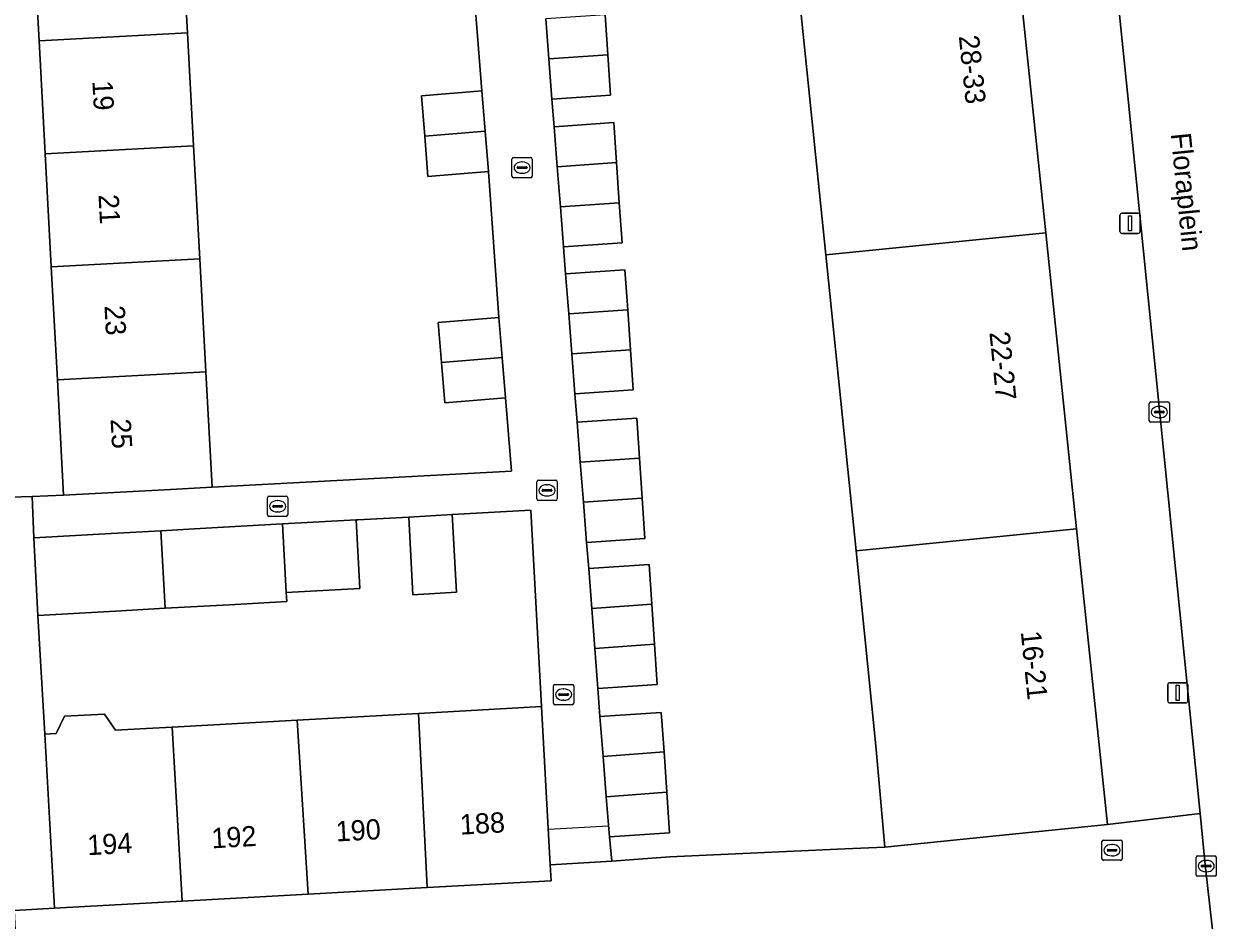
# Model space of a CAD drawing. Extents: x 162250 to 162661, y 380743 to 381606.
# Drawn here: x 162500.7 to 162559.6, y 380777.6 to 380821.9 of the extents above; entities that cross this region are included whole.
import ezdxf

# ---------------------------------------------------------------- set-up
doc = ezdxf.new("R2010")
doc.units = 0
for name, color, linetype in [('IMGEO_Brandkraan', 7, 'Continuous'), ('IMGEO_Erf', 7, 'Continuous'), ('IMGEO_Hek', 7, 'Continuous'), ('IMGEO_Kolk', 7, 'Continuous'), ('IMGEO_Lichtmast', 7, 'Continuous'), ('IMGEO_Muur', 7, 'Continuous'), ('IMGEO_Openbare_ruimte_label', 7, 'Continuous'), ('IMGEO_Pand', 7, 'Continuous'), ('IMGEO_Pand_nummerreeks', 7, 'Continuous'), ('IMGEO_Rijbaan_lokaal_open', 7, 'Continuous'), ('IMGEO_Voetpad_open', 7, 'Continuous')]:
    doc.layers.add(name, color=color, linetype=linetype)

msp = doc.modelspace()

# ---------------------------------------------------------------- linework, layer by layer
at = {"layer": 'IMGEO_Brandkraan'}
for p, q in [((162553.929, 380780.603), (162553.929, 380781.455)), ((162554.004, 380781.529), (162554.856, 380781.529)), ((162554.93, 380781.455), (162554.93, 380780.603)), ((162554.188, 380781.023), (162554.188, 380781.035)), ((162554.626, 380780.986), (162554.228, 380780.986)), ((162554.231, 380781.072), (162554.629, 380781.072)), ((162554.417, 380781.309), (162554.442, 380781.309)), ((162554.672, 380781.035), (162554.672, 380781.023)), ((162554.856, 380780.529), (162554.004, 380780.529)), ((162554.44, 380780.749), (162554.415, 380780.749))]:
    msp.add_line(p, q, dxfattribs=at)
for points in [[(162553.929, 380780.603), (162553.929, 380781.455)], [(162554.004, 380781.529), (162554.856, 380781.529)], [(162554.93, 380781.455), (162554.93, 380780.603)], [(162554.856, 380780.529), (162554.004, 380780.529)]]:
    msp.add_lwpolyline(points, dxfattribs=at)
for centre, radius, start, end in [((162554.006, 380781.453), 0.0765, 91.55205, 178.44795), ((162554.006, 380781.453), 0.0765, 91.55205, 178.44795), ((162554.854, 380781.453), 0.0765, 1.55205, 88.44795), ((162554.854, 380781.453), 0.0765, 1.55205, 88.44795), ((162554.228, 380781.032), 0.0403, 85.87752, 175.75265), ((162554.225, 380781.022), 0.0366, 178.93798, 274.71019), ((162554.629, 380781.029), 0.043, 264.86636, 352.45326), ((162554.633, 380781.034), 0.0386, 1.73085, 96.63898), ((162554.006, 380780.605), 0.0765, 181.55205, 268.44795), ((162554.006, 380780.605), 0.0765, 181.55205, 268.44795), ((162554.854, 380780.605), 0.0765, 271.55205, 358.44795), ((162554.854, 380780.605), 0.0765, 271.55205, 358.44795)]:
    msp.add_arc(centre, radius, start, end, dxfattribs=at)
for centre, major_axis, ratio, start_param, end_param in [((162554.416, 380781.029), (-0.387, 0.002), 0.722429, 4.712389, 7.853982), ((162554.441, 380781.029), (-0.39, 0.002), 0.717154, 1.570796, 4.712389)]:
    msp.add_ellipse(centre, major_axis=major_axis, ratio=ratio, start_param=start_param, end_param=end_param, dxfattribs=at)
at = {"layer": 'IMGEO_Erf'}
for points in [[(162500.535, 380837.761), (162500.235, 380843.344), (162500, 380847.679), (162499.934, 380848.927), (162499.634, 380854.509), (162499.333, 380860.091), (162499.032, 380865.673), (162498.723, 380871.373), (162496.735, 380871.229), (162495.691, 380871.164), (162499.625, 380798.455), (162500, 380798.466), (162501.095, 380798.5), (162502.647, 380798.565), (162502.34, 380804.267), (162502.039, 380809.849), (162501.738, 380815.432), (162501.437, 380821.014), (162501.136, 380826.596), (162500.835, 380832.179)], [(162525.72, 380797.824), (162521.84, 380797.61), (162522.052, 380793.775), (162519.891, 380793.655), (162519.7, 380797.492), (162517.176, 380797.352), (162517.097, 380797.348), (162517.284, 380793.96), (162513.649, 380793.759), (162513.674, 380793.313), (162510.849, 380793.157), (162507.673, 380792.981), (162505.216, 380792.845), (162501.383, 380792.633), (162501.726, 380786.77), (162502.28, 380786.8), (162502.694, 380787.646), (162504.665, 380787.754), (162505.219, 380786.961), (162506.735, 380787.044), (162508.012, 380787.115), (162514.19, 380787.456), (162520.184, 380787.787), (162526.255, 380788.122)]]:
    msp.add_lwpolyline(points, close=True, dxfattribs=at)
for points in [[(162508.463, 380826.992), (162508.766, 380821.409), (162509.07, 380815.828), (162509.373, 380810.246), (162509.676, 380804.664), (162509.986, 380798.963), (162524.762, 380799.763), (162524.467, 380803.379), (162521.477, 380803.135), (162521.315, 380805.122), (162521.153, 380807.109), (162524.143, 380807.353), (162523.636, 380814.568), (162520.646, 380814.324), (162520.484, 380816.311), (162520.322, 380818.298), (162523.312, 380818.542), (162522.731, 380825.847)], [(162529.396, 380822.302), (162529.531, 380820.322), (162529.666, 380818.342), (162526.77, 380818.142), (162526.876, 380816.777), (162529.825, 380816.981), (162529.96, 380815.001), (162530.095, 380813.021), (162530.23, 380811.041), (162527.337, 380810.844), (162527.441, 380809.503), (162530.374, 380809.709), (162530.509, 380807.729), (162530.644, 380805.749), (162530.779, 380803.769), (162527.902, 380803.573), (162528.01, 380802.18), (162530.953, 380802.378), (162531.088, 380800.398), (162531.223, 380798.418), (162531.358, 380796.438), (162528.472, 380796.238), (162528.589, 380794.948), (162531.562, 380795.151), (162531.696, 380793.19), (162531.831, 380791.21), (162531.967, 380789.211), (162529.033, 380789.011), (162529.141, 380787.631), (162532.17, 380787.835), (162532.303, 380785.885), (162532.438, 380783.904), (162532.575, 380781.895), (162529.602, 380781.692), (162529.724, 380780.491), (162532.594, 380780.706), (162541.237, 380781.095), (162543.214, 380781.184), (162542.767, 380786.192), (162541.786, 380795.815), (162540.295, 380810.439), (162538.803, 380825.063)]]:
    msp.add_lwpolyline(points, dxfattribs=at)
at = {"layer": 'IMGEO_Hek'}
msp.add_lwpolyline([(162529.566, 380782.219), (162526.59, 380782.049)], dxfattribs=at)
at = {"layer": 'IMGEO_Kolk'}
for p, q in [((162524.794, 380814.329), (162524.794, 380815.181)), ((162524.869, 380815.255), (162525.721, 380815.255)), ((162525.282, 380815.035), (162525.307, 380815.035)), ((162525.795, 380815.181), (162525.795, 380814.329)), ((162525.053, 380814.749), (162525.053, 380814.761)), ((162525.491, 380814.712), (162525.093, 380814.712)), ((162525.096, 380814.798), (162525.494, 380814.798)), ((162525.305, 380814.475), (162525.28, 380814.475)), ((162525.537, 380814.761), (162525.537, 380814.749)), ((162525.721, 380814.255), (162524.869, 380814.255)), ((162556.267, 380802.249), (162556.267, 380803.101)), ((162556.342, 380803.175), (162557.194, 380803.175)), ((162556.526, 380802.669), (162556.526, 380802.681)), ((162556.964, 380802.632), (162556.566, 380802.632)), ((162556.569, 380802.718), (162556.967, 380802.718)), ((162556.755, 380802.955), (162556.78, 380802.955)), ((162557.01, 380802.681), (162557.01, 380802.669)), ((162557.268, 380803.101), (162557.268, 380802.249)), ((162557.194, 380802.175), (162556.342, 380802.175)), ((162556.778, 380802.395), (162556.753, 380802.395)), ((162526.026, 380798.384), (162526.026, 380799.236)), ((162526.101, 380799.31), (162526.953, 380799.31)), ((162526.514, 380799.09), (162526.539, 380799.09)), ((162527.027, 380799.236), (162527.027, 380798.384)), ((162512.793, 380798.521), (162513.645, 380798.521)), ((162526.285, 380798.804), (162526.285, 380798.816)), ((162526.723, 380798.767), (162526.325, 380798.767)), ((162526.328, 380798.853), (162526.726, 380798.853)), ((162526.537, 380798.53), (162526.512, 380798.53)), ((162526.769, 380798.816), (162526.769, 380798.804)), ((162512.718, 380797.595), (162512.718, 380798.447)), ((162512.977, 380798.015), (162512.977, 380798.027)), ((162513.415, 380797.978), (162513.017, 380797.978)), ((162513.02, 380798.064), (162513.418, 380798.064)), ((162513.206, 380798.301), (162513.231, 380798.301)), ((162513.461, 380798.027), (162513.461, 380798.015)), ((162513.719, 380798.447), (162513.719, 380797.595)), ((162526.953, 380798.31), (162526.101, 380798.31)), ((162513.645, 380797.521), (162512.793, 380797.521)), ((162513.229, 380797.741), (162513.204, 380797.741)), ((162526.842, 380788.293), (162526.842, 380789.145)), ((162526.917, 380789.219), (162527.769, 380789.219)), ((162527.843, 380789.145), (162527.843, 380788.293)), ((162527.101, 380788.713), (162527.101, 380788.725)), ((162527.539, 380788.676), (162527.141, 380788.676)), ((162527.144, 380788.762), (162527.542, 380788.762)), ((162527.33, 380788.999), (162527.355, 380788.999)), ((162527.585, 380788.725), (162527.585, 380788.713)), ((162527.769, 380788.219), (162526.917, 380788.219)), ((162527.353, 380788.439), (162527.328, 380788.439)), ((162558.58, 380779.817), (162558.58, 380780.669)), ((162558.655, 380780.743), (162559.507, 380780.743)), ((162558.839, 380780.237), (162558.839, 380780.249)), ((162558.882, 380780.286), (162559.28, 380780.286)), ((162559.068, 380780.523), (162559.093, 380780.523)), ((162559.323, 380780.249), (162559.323, 380780.237)), ((162559.581, 380780.669), (162559.581, 380779.817)), ((162559.507, 380779.743), (162558.655, 380779.743)), ((162559.277, 380780.2), (162558.879, 380780.2)), ((162559.091, 380779.963), (162559.066, 380779.963))]:
    msp.add_line(p, q, dxfattribs=at)
for points in [[(162524.794, 380814.329), (162524.794, 380815.181)], [(162524.869, 380815.255), (162525.721, 380815.255)], [(162525.795, 380815.181), (162525.795, 380814.329)], [(162525.721, 380814.255), (162524.869, 380814.255)], [(162556.267, 380802.249), (162556.267, 380803.101)], [(162556.342, 380803.175), (162557.194, 380803.175)], [(162557.268, 380803.101), (162557.268, 380802.249)], [(162557.194, 380802.175), (162556.342, 380802.175)], [(162526.026, 380798.384), (162526.026, 380799.236)], [(162526.101, 380799.31), (162526.953, 380799.31)], [(162527.027, 380799.236), (162527.027, 380798.384)], [(162512.793, 380798.521), (162513.645, 380798.521)], [(162512.718, 380797.595), (162512.718, 380798.447)], [(162513.719, 380798.447), (162513.719, 380797.595)], [(162526.953, 380798.31), (162526.101, 380798.31)], [(162513.645, 380797.521), (162512.793, 380797.521)], [(162526.842, 380788.293), (162526.842, 380789.145)], [(162526.917, 380789.219), (162527.769, 380789.219)], [(162527.843, 380789.145), (162527.843, 380788.293)], [(162527.769, 380788.219), (162526.917, 380788.219)], [(162558.58, 380779.817), (162558.58, 380780.669)], [(162558.655, 380780.743), (162559.507, 380780.743)], [(162559.581, 380780.669), (162559.581, 380779.817)], [(162559.507, 380779.743), (162558.655, 380779.743)]]:
    msp.add_lwpolyline(points, dxfattribs=at)
for centre, radius, start, end in [((162524.871, 380815.179), 0.0765, 91.55205, 178.44795), ((162524.871, 380815.179), 0.0765, 91.55205, 178.44795), ((162525.719, 380815.179), 0.0765, 1.55205, 88.44795), ((162525.719, 380815.179), 0.0765, 1.55205, 88.44795), ((162525.093, 380814.758), 0.0403, 85.87752, 175.75265), ((162525.09, 380814.748), 0.0366, 178.93798, 274.71019), ((162525.494, 380814.755), 0.043, 264.86636, 352.45326), ((162525.498, 380814.76), 0.0386, 1.73085, 96.63898), ((162524.871, 380814.331), 0.0765, 181.55205, 268.44795), ((162524.871, 380814.331), 0.0765, 181.55205, 268.44795), ((162525.719, 380814.331), 0.0765, 271.55205, 358.44795), ((162525.719, 380814.331), 0.0765, 271.55205, 358.44795), ((162556.344, 380803.099), 0.0765, 91.55205, 178.44795), ((162556.344, 380803.099), 0.0765, 91.55205, 178.44795), ((162556.566, 380802.678), 0.0403, 85.87752, 175.75265), ((162556.563, 380802.668), 0.0366, 178.93798, 274.71019), ((162556.967, 380802.675), 0.043, 264.86636, 352.45326), ((162556.971, 380802.68), 0.0386, 1.73085, 96.63898), ((162557.192, 380803.099), 0.0765, 1.55205, 88.44795), ((162557.192, 380803.099), 0.0765, 1.55205, 88.44795), ((162556.344, 380802.251), 0.0765, 181.55205, 268.44795), ((162556.344, 380802.251), 0.0765, 181.55205, 268.44795), ((162557.192, 380802.251), 0.0765, 271.55205, 358.44795), ((162557.192, 380802.251), 0.0765, 271.55205, 358.44795), ((162526.103, 380799.234), 0.0765, 91.55205, 178.44795), ((162526.103, 380799.234), 0.0765, 91.55205, 178.44795), ((162526.951, 380799.234), 0.0765, 1.55205, 88.44795), ((162526.951, 380799.234), 0.0765, 1.55205, 88.44795), ((162512.795, 380798.445), 0.0765, 91.55205, 178.44795), ((162512.795, 380798.445), 0.0765, 91.55205, 178.44795), ((162513.643, 380798.445), 0.0765, 1.55205, 88.44795), ((162513.643, 380798.445), 0.0765, 1.55205, 88.44795), ((162526.325, 380798.813), 0.0403, 85.87752, 175.75265), ((162526.322, 380798.803), 0.0366, 178.93798, 274.71019), ((162526.726, 380798.81), 0.043, 264.86636, 352.45326), ((162526.73, 380798.815), 0.0386, 1.73085, 96.63898), ((162513.017, 380798.024), 0.0403, 85.87752, 175.75265), ((162513.014, 380798.014), 0.0366, 178.93798, 274.71019), ((162513.418, 380798.021), 0.043, 264.86636, 352.45326), ((162513.422, 380798.026), 0.0386, 1.73085, 96.63898), ((162526.103, 380798.386), 0.0765, 181.55205, 268.44795), ((162526.103, 380798.386), 0.0765, 181.55205, 268.44795), ((162526.951, 380798.386), 0.0765, 271.55205, 358.44795), ((162526.951, 380798.386), 0.0765, 271.55205, 358.44795), ((162512.795, 380797.597), 0.0765, 181.55205, 268.44795), ((162512.795, 380797.597), 0.0765, 181.55205, 268.44795), ((162513.643, 380797.597), 0.0765, 271.55205, 358.44795), ((162513.643, 380797.597), 0.0765, 271.55205, 358.44795), ((162526.919, 380789.143), 0.0765, 91.55205, 178.44795), ((162526.919, 380789.143), 0.0765, 91.55205, 178.44795), ((162527.767, 380789.143), 0.0765, 1.55205, 88.44795), ((162527.767, 380789.143), 0.0765, 1.55205, 88.44795), ((162527.141, 380788.722), 0.0403, 85.87752, 175.75265), ((162527.138, 380788.712), 0.0366, 178.93798, 274.71019), ((162527.542, 380788.719), 0.043, 264.86636, 352.45326), ((162527.546, 380788.724), 0.0386, 1.73085, 96.63898), ((162526.919, 380788.295), 0.0765, 181.55205, 268.44795), ((162526.919, 380788.295), 0.0765, 181.55205, 268.44795), ((162527.767, 380788.295), 0.0765, 271.55205, 358.44795), ((162527.767, 380788.295), 0.0765, 271.55205, 358.44795), ((162558.657, 380780.667), 0.0765, 91.55205, 178.44795), ((162558.657, 380780.667), 0.0765, 91.55205, 178.44795), ((162558.879, 380780.246), 0.0403, 85.87752, 175.75265), ((162558.876, 380780.236), 0.0366, 178.93798, 274.71019), ((162559.28, 380780.243), 0.043, 264.86636, 352.45326), ((162559.284, 380780.248), 0.0386, 1.73085, 96.63898), ((162559.505, 380780.667), 0.0765, 1.55205, 88.44795), ((162559.505, 380780.667), 0.0765, 1.55205, 88.44795), ((162558.657, 380779.819), 0.0765, 181.55205, 268.44795), ((162558.657, 380779.819), 0.0765, 181.55205, 268.44795), ((162559.505, 380779.819), 0.0765, 271.55205, 358.44795), ((162559.505, 380779.819), 0.0765, 271.55205, 358.44795)]:
    msp.add_arc(centre, radius, start, end, dxfattribs=at)
for centre, major_axis, ratio, start_param, end_param in [((162525.281, 380814.755), (-0.387, 0.002), 0.722429, 4.712389, 7.853982), ((162525.306, 380814.755), (-0.39, 0.002), 0.717154, 1.570796, 4.712389), ((162556.754, 380802.675), (-0.387, 0.002), 0.722429, 4.712389, 7.853982), ((162556.779, 380802.675), (-0.39, 0.002), 0.717154, 1.570796, 4.712389), ((162526.513, 380798.81), (-0.387, 0.002), 0.722429, 4.712389, 7.853982), ((162526.538, 380798.81), (-0.39, 0.002), 0.717154, 1.570796, 4.712389), ((162513.205, 380798.021), (-0.387, 0.002), 0.722429, 4.712389, 7.853982), ((162513.23, 380798.021), (-0.39, 0.002), 0.717154, 1.570796, 4.712389), ((162527.329, 380788.719), (-0.387, 0.002), 0.722429, 4.712389, 7.853982), ((162527.354, 380788.719), (-0.39, 0.002), 0.717154, 1.570796, 4.712389), ((162559.067, 380780.243), (-0.387, 0.002), 0.722429, 4.712389, 7.853982), ((162559.092, 380780.243), (-0.39, 0.002), 0.717154, 1.570796, 4.712389)]:
    msp.add_ellipse(centre, major_axis=major_axis, ratio=ratio, start_param=start_param, end_param=end_param, dxfattribs=at)
at = {"layer": 'IMGEO_Lichtmast'}
for p, q in [((162554.822, 380811.603), (162554.822, 380812.403)), ((162554.822, 380812.403), (162554.822, 380811.603)), ((162554.922, 380812.503), (162555.712, 380812.503)), ((162555.712, 380812.503), (162554.922, 380812.503)), ((162555.812, 380812.403), (162555.812, 380811.603)), ((162555.812, 380811.603), (162555.812, 380812.403)), ((162555.712, 380811.503), (162554.922, 380811.503)), ((162554.922, 380811.503), (162555.712, 380811.503)), ((162557.182, 380788.406), (162557.182, 380789.206)), ((162557.182, 380789.206), (162557.182, 380788.406)), ((162557.282, 380789.306), (162558.072, 380789.306)), ((162558.072, 380789.306), (162557.282, 380789.306)), ((162558.172, 380789.206), (162558.172, 380788.406)), ((162558.172, 380788.406), (162558.172, 380789.206)), ((162558.072, 380788.306), (162557.282, 380788.306)), ((162557.282, 380788.306), (162558.072, 380788.306))]:
    msp.add_line(p, q, dxfattribs=at)
for points in [[(162555.242, 380812.378), (162555.392, 380812.378), (162555.392, 380811.628), (162555.242, 380811.628), (162555.242, 380812.378)], [(162557.602, 380789.181), (162557.752, 380789.181), (162557.752, 380788.431), (162557.602, 380788.431), (162557.602, 380789.181)]]:
    msp.add_lwpolyline(points, dxfattribs=at)
for centre, start, end in [((162554.922, 380812.403), 90, 180), ((162554.922, 380812.403), 90, 180), ((162555.712, 380812.403), 0, 90), ((162555.712, 380812.403), 360, 90), ((162554.922, 380811.603), 180, 270), ((162554.922, 380811.603), 180, 270), ((162555.712, 380811.603), 270, 0), ((162555.712, 380811.603), 270, 0), ((162557.282, 380789.206), 90, 180), ((162557.282, 380789.206), 90, 180), ((162558.072, 380789.206), 0, 90), ((162558.072, 380789.206), 360, 90), ((162557.282, 380788.406), 180, 270), ((162557.282, 380788.406), 180, 270), ((162558.072, 380788.406), 270, 0), ((162558.072, 380788.406), 270, 0)]:
    msp.add_arc(centre, 0.1, start, end, dxfattribs=at)
at = {"layer": 'IMGEO_Muur'}
for points in [[(162501.383, 380792.633), (162501.726, 380786.77)], [(162541.237, 380781.095), (162543.214, 380781.184)]]:
    msp.add_lwpolyline(points, dxfattribs=at)
at = {"layer": 'IMGEO_Pand'}
for points in [[(162508.463, 380826.992), (162501.136, 380826.596), (162501.437, 380821.014), (162508.766, 380821.409)], [(162551.156, 380811.537), (162549.634, 380826.158), (162538.803, 380825.063), (162540.295, 380810.439)], [(162529.396, 380822.302), (162526.462, 380822.102), (162526.616, 380820.123), (162529.531, 380820.322)], [(162508.766, 380821.409), (162501.437, 380821.014), (162501.738, 380815.432), (162509.07, 380815.828)], [(162529.531, 380820.322), (162526.616, 380820.123), (162526.77, 380818.142), (162529.666, 380818.342)], [(162523.312, 380818.542), (162520.322, 380818.298), (162520.484, 380816.311), (162523.474, 380816.555)], [(162529.825, 380816.981), (162526.876, 380816.777), (162527.03, 380814.801), (162529.96, 380815.001)], [(162523.474, 380816.555), (162520.484, 380816.311), (162520.646, 380814.324), (162523.636, 380814.568)], [(162501.738, 380815.432), (162502.039, 380809.849), (162509.373, 380810.246), (162509.07, 380815.828)], [(162529.96, 380815.001), (162527.03, 380814.801), (162527.183, 380812.822), (162530.095, 380813.021)], [(162530.095, 380813.021), (162527.183, 380812.822), (162527.337, 380810.844), (162530.23, 380811.041)], [(162551.156, 380811.537), (162540.295, 380810.439), (162541.786, 380795.815), (162552.678, 380796.916)], [(162509.676, 380804.664), (162509.373, 380810.246), (162502.039, 380809.849), (162502.34, 380804.267)], [(162530.374, 380809.709), (162527.441, 380809.503), (162527.594, 380807.53), (162530.509, 380807.729)], [(162524.143, 380807.353), (162521.153, 380807.109), (162521.315, 380805.122), (162524.305, 380805.366)], [(162530.509, 380807.729), (162527.594, 380807.53), (162527.748, 380805.552), (162530.644, 380805.749)], [(162530.644, 380805.749), (162527.748, 380805.552), (162527.902, 380803.573), (162530.779, 380803.769)], [(162524.305, 380805.366), (162521.315, 380805.122), (162521.477, 380803.135), (162524.467, 380803.379)], [(162509.676, 380804.664), (162502.34, 380804.267), (162502.647, 380798.565), (162507.64, 380798.836), (162509.986, 380798.963)], [(162530.953, 380802.378), (162528.01, 380802.18), (162528.164, 380800.199), (162531.088, 380800.398)], [(162531.088, 380800.398), (162528.164, 380800.199), (162528.318, 380798.22), (162531.223, 380798.418)], [(162531.223, 380798.418), (162528.318, 380798.22), (162528.472, 380796.238), (162531.358, 380796.438)], [(162517.097, 380797.348), (162513.462, 380797.148), (162513.649, 380793.759), (162517.284, 380793.96)], [(162519.7, 380797.492), (162519.891, 380793.655), (162522.052, 380793.775), (162521.84, 380797.61)], [(162507.673, 380792.981), (162507.451, 380796.815), (162505.004, 380796.68), (162501.171, 380796.468), (162501.383, 380792.633), (162505.216, 380792.845)], [(162513.462, 380797.148), (162509.668, 380796.938), (162507.451, 380796.815), (162507.673, 380792.981), (162510.849, 380793.157), (162513.674, 380793.313), (162513.649, 380793.759)], [(162541.786, 380795.815), (162542.767, 380786.192), (162543.214, 380781.184), (162554.2, 380782.295), (162552.678, 380796.916)], [(162528.589, 380794.948), (162528.737, 380792.969), (162531.696, 380793.19), (162531.562, 380795.151)], [(162531.696, 380793.19), (162528.737, 380792.969), (162528.885, 380790.99), (162531.831, 380791.21)], [(162531.831, 380791.21), (162528.885, 380790.99), (162529.033, 380789.011), (162531.967, 380789.211)], [(162520.184, 380787.787), (162520.613, 380779.182), (162526.73, 380779.52), (162526.687, 380780.301), (162526.454, 380784.513), (162526.255, 380788.122)], [(162508.012, 380787.115), (162506.735, 380787.044), (162505.219, 380786.961), (162504.665, 380787.754), (162502.694, 380787.646), (162502.28, 380786.8), (162501.726, 380786.77), (162502.201, 380778.165), (162508.51, 380778.514)], [(162508.012, 380787.115), (162508.51, 380778.514), (162514.735, 380778.857), (162514.19, 380787.456)], [(162520.184, 380787.787), (162514.19, 380787.456), (162514.735, 380778.857), (162520.613, 380779.182)], [(162529.141, 380787.631), (162529.295, 380785.651), (162532.303, 380785.885), (162532.17, 380787.835)], [(162532.303, 380785.885), (162529.295, 380785.651), (162529.448, 380783.672), (162532.438, 380783.904)], [(162532.438, 380783.904), (162529.448, 380783.672), (162529.602, 380781.692), (162532.575, 380781.895)]]:
    msp.add_lwpolyline(points, close=True, dxfattribs=at)
at = {"layer": 'IMGEO_Rijbaan_lokaal_open'}
msp.add_lwpolyline([(162556.408, 380848.385), (162556.384, 380848.613), (162556.077, 380851.576), (162555.417, 380857.25), (162555.382, 380857.554), (162550.999, 380857.103), (162551.063, 380856.512), (162551.932, 380848.95), (162553.575, 380834.204), (162555.189, 380818.45), (162558.777, 380782.848), (162559.034, 380780.302), (162559.621, 380775.057), (162559.501, 380773.592)], dxfattribs=at)
at = {"layer": 'IMGEO_Voetpad_open'}
for points in [[(162539.795, 380900.36), (162540.416, 380896.616), (162547.18, 380863.294), (162546.206, 380863.09), (162545.78, 380863.003), (162539.252, 380861.677), (162539.001, 380861.626), (162539.128, 380860.542), (162523.79, 380859.034), (162524.418, 380853.206), (162527.021, 380853.383), (162535.821, 380854.312), (162541.615, 380854.91), (162546.588, 380855.422), (162548.112, 380840.779), (162549.634, 380826.158), (162551.156, 380811.537), (162552.678, 380796.916), (162554.2, 380782.295), (162558.777, 380782.848), (162555.189, 380818.45), (162553.575, 380834.204), (162551.932, 380848.95)], [(162496.225, 380798.581), (162496.36, 380795.645), (162496.445, 380793.785), (162496.544, 380791.858), (162499.481, 380792.01), (162499.931, 380782.983), (162500.205, 380778.05), (162502.201, 380778.165), (162501.726, 380786.77), (162501.383, 380792.633), (162501.171, 380796.468), (162501.095, 380798.5), (162500, 380798.466), (162499.625, 380798.455), (162495.691, 380871.164)], [(162522.731, 380825.847), (162523.312, 380818.542), (162523.474, 380816.555), (162523.636, 380814.568), (162524.143, 380807.353), (162524.305, 380805.366), (162524.467, 380803.379), (162524.762, 380799.763), (162509.986, 380798.963), (162507.64, 380798.836), (162502.647, 380798.565), (162501.095, 380798.5), (162501.171, 380796.468), (162505.004, 380796.68), (162507.451, 380796.815), (162509.668, 380796.938), (162513.462, 380797.148), (162517.097, 380797.348), (162517.176, 380797.352), (162519.7, 380797.492), (162521.84, 380797.61), (162525.72, 380797.824), (162526.255, 380788.122), (162526.454, 380784.513), (162526.687, 380780.301), (162529.724, 380780.491), (162529.602, 380781.692), (162529.448, 380783.672), (162529.295, 380785.651), (162529.141, 380787.631), (162529.033, 380789.011), (162528.885, 380790.99), (162528.737, 380792.969), (162528.589, 380794.948), (162528.472, 380796.238), (162528.318, 380798.22), (162528.164, 380800.199), (162528.01, 380802.18), (162527.902, 380803.573), (162527.748, 380805.552), (162527.594, 380807.53), (162527.441, 380809.503), (162527.337, 380810.844), (162527.183, 380812.822), (162527.03, 380814.801), (162526.876, 380816.777), (162526.77, 380818.142), (162526.616, 380820.123), (162526.462, 380822.102)], [(162559.501, 380773.592), (162559.621, 380775.057), (162559.034, 380780.302), (162558.777, 380782.848), (162554.2, 380782.295), (162543.214, 380781.184), (162541.237, 380781.095), (162532.594, 380780.706), (162529.724, 380780.491), (162526.687, 380780.301), (162526.73, 380779.52), (162520.613, 380779.182), (162514.735, 380778.857), (162508.51, 380778.514), (162502.201, 380778.165), (162500.205, 380778.05), (162500.277, 380776.758), (162497.317, 380776.685), (162497.528, 380772.494), (162497.631, 380770.094), (162494.252, 380769.964), (162494.089, 380773.04)]]:
    msp.add_lwpolyline(points, dxfattribs=at)

# ---------------------------------------------------------------- texts
at = {"layer": 'IMGEO_Openbare_ruimte_label'}
msp.add_text('Floraplein', height=1, rotation=275.7391, dxfattribs=at).set_placement((162557.323, 380816.429))
at = {"layer": 'IMGEO_Pand_nummerreeks'}
for s, rotation, p in [('28-33', 275.94686, (162546.859, 380821.257)), ('19', 273.08498, (162504.067, 380819.037)), ('21', 273.08498, (162504.37, 380813.415)), ('23', 273.08498, (162504.666, 380807.927)), ('22-27', 275.79525, (162548.372, 380806.612)), ('25', 273.08498, (162504.968, 380802.326)), ('16-21', 275.79525, (162549.921, 380791.823)), ('190', 3.16185, (162516.111, 380781.456)), ('188', 3.16185, (162522.243, 380781.795)), ('192', 3.16185, (162509.972, 380781.118)), ('194', 3.16273, (162503.842, 380780.779))]:
    msp.add_text(s, height=1, rotation=rotation, dxfattribs=at).set_placement(p)

doc.saveas('drawing.dxf')
